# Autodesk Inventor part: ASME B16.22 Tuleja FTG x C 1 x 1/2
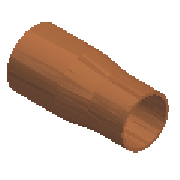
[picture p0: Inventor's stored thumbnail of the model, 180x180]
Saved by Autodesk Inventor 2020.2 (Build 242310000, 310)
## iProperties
NAME: PIPING: ASME B16.22 Bushing FTG x C
DATA: <meta><inlinegroups number="1" deflen="2.54"></inlinegroups><connections number="2"></connections><angles><a>3.14159265358979</a></angles></meta>
Manager: www.cadconsulting.pl
Company: Fabian Stasiak CAD Consulting
Created: 2014-02
Part Number: ASME B16.22 Tuleja FTG x C 1 x 1/2
Material: Miedź kuta
Description: Tuleja
Document SubType Name: Modeling
Standard: ASME B16.22
Designer: F.Stasiak
Standard Revision: 2001
Standards Organization: ANSI
Language: pl-PL
Size Designation: 1 x 1/2
Categories: <MemberInstance><Categories><Category DisplayName="Rury cienko- i grubościenne" InternalName="4347fa0f-2144-441d-94cd-e3e15c92b736" Mnemonic="TUBEANDPIPE"><Cate
Density: 1 g/cm^3
Appearance: Miedź - satynowa
Catalog Web Link: www.expertbooks.pl
IsCustomPart: 0
Author: F.Stasiak
Subject: Zbiór ćwiczeń. Autodesk Inventor 2020. Kurs Professional
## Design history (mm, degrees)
sketch "Sketch1"
  geometry: L1 (0, 0)-(-50.8, 0); L2 (0, 0)-(0, 13.233); L3 (0, 13.233)-(0, 14.249); L4 (0, 14.249)-(-24.638, 14.249); L5 (-24.638, 14.249)-(-38.1, 8.699); L6 (-38.1, 8.699)-(-50.8, 8.699); L7 (-50.8, 8.699)-(-50.8, 7.963); L8 (-50.8, 7.963)-(-38.215, 7.963); L9 (-24.638, 13.233)-(0, 13.233); L10 (-50.8, 7.963)-(-50.8, 0); L11 (-38.1, 8.699)-(-38.1, 0); L12 (-24.638, 14.249)-(-24.638, 13.233); L13 (-38.1, 7.683)-(-24.638, 13.233); L14 (-38.1, 7.683)-(-38.215, 7.963); L15 (-24.638, 13.233)-(-24.638, 0); 1 further point
  constraints: 30 end point, 6 perpendicular, 5 parallel, 3 point on line, 1 coincident, 1 collinear, 1 horizontal
  dimensions: "d0" = 0.7366 distance of L6.end L7.end (= T2); "d1" = 1.016 distance of L2.end L3.end (= T1); "d2" = 14.2494 distance of L1.start L3.end (= 0.5 x A); "d3" = 7.9629 distance of L7.end L1.end (= 0.5 x F1); "d4" = 12.7 distance of L11.end L1.end (= G); "d5" = 24.638 horizontal distance of L9.start L1.start (= K1); "d6" = 38.1 distance of L1.start L11.end (= L); "d7" = 1.016 distance of L13.start L5.end (= T1)
revolve "Revolve1" sketch "Sketch1" stored, may be unused: angle "d9" = 90 deg
workpoint "Work Point1"
workpoint "Work Point2"
workaxis "Work Axis1"
workpoint "Work Point3"
workaxis "Work Axis2"
workpoint "Work Point4"
body "Solid1"
other parameters: "L" = 38.1 [user parameter; used in 1 equation term], "G" = 12.7 [user parameter; used in 1 equation term], "T1" = 1.016 [user parameter; used in 2 equation terms], "F1" = 15.9258 [user parameter; used in 1 equation term], "A" = 28.4988 [user parameter; used in 1 equation term], "T2" = 0.7366 [user parameter; used in 1 equation term], "K1" = 24.638 [user parameter; used in 1 equation term], "Size_Designation" = 12.345 [user parameter]
